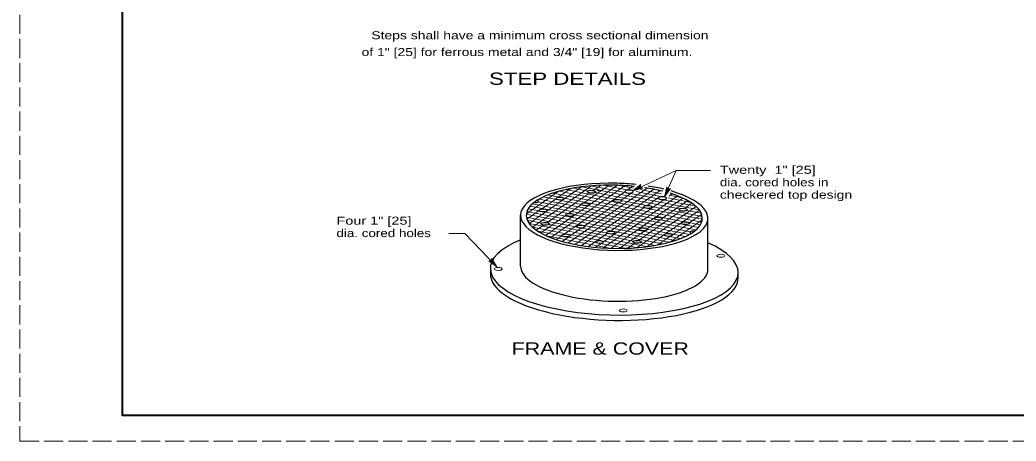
# Model space of a CAD drawing. Extents: x 1083.1 to 1117.1, y 697.4 to 741.4.
# Drawn here: x 1083.13 to 1102.54, y 697.35 to 705.57 of the extents above; entities that cross this region are included whole.
import ezdxf

# ---------------------------------------------------------------- set-up
doc = ezdxf.new("R2010")
doc.units = 0
doc.header["$LTSCALE"] = 0.062
doc.header["$PDMODE"] = 32
doc.header["$PDSIZE"] = 0.031
doc.linetypes.add('LONG_DASHED', pattern=[7.5, 6, -1.5])
doc.layers.add('1', color=7, linetype='Continuous', lineweight=13)

msp = doc.modelspace()

# ---------------------------------------------------------------- linework, layer by layer
at = {"layer": '1'}
for p, q in [((1095.07342, 702.23525), (1095.91408, 702.62967)), ((1095.69267, 702.11442), (1095.91408, 702.62967)), ((1095.91408, 702.62967), (1096.58942, 702.62967)), ((1093.05142, 701.59733), (1094.07375, 702.31042)), ((1093.11458, 701.52725), (1094.26708, 702.33117)), ((1093.37175, 701.36433), (1094.77217, 702.34108)), ((1093.47342, 701.32117), (1094.92583, 702.33417)), ((1093.61942, 702.10767), (1093.8635, 702.27783)), ((1093.81517, 701.21717), (1095.35017, 702.28783)), ((1093.91967, 702.28408), (1094.19808, 702.2295)), ((1094.08808, 702.30842), (1096.3665, 701.86133)), ((1094.11708, 701.99833), (1094.61067, 702.34258)), ((1094.95325, 702.19608), (1094.28575, 702.32708)), ((1094.30233, 702.24167), (1094.44392, 702.34042)), ((1094.50833, 702.34067), (1094.9835, 702.24742)), ((1094.80358, 702.34008), (1095.084, 702.28508)), ((1094.962, 702.24533), (1095.07308, 702.32275)), ((1095.22042, 702.33558), (1095.07342, 702.23525)), ((1095.2205, 702.322), (1095.07342, 702.23525)), ((1095.22442, 702.31), (1095.07342, 702.23525)), ((1095.23425, 702.29717), (1095.07342, 702.23525)), ((1095.24533, 702.28992), (1095.07342, 702.23525)), ((1095.74058, 702.28583), (1095.69267, 702.11442)), ((1095.74942, 702.2755), (1095.69267, 702.11442)), ((1095.76008, 702.26883), (1095.69267, 702.11442)), ((1095.789, 702.267), (1095.69267, 702.11442)), ((1092.99708, 701.78767), (1093.61467, 702.21842)), ((1093.291, 701.87858), (1093.57642, 702.07767)), ((1093.327, 702.11358), (1094.06642, 701.9685)), ((1093.40358, 701.61475), (1094.23233, 702.19283)), ((1093.4185, 702.153), (1093.63917, 702.10967)), ((1093.52167, 702.19017), (1093.91467, 702.113)), ((1093.63758, 702.22475), (1094.017, 702.15025)), ((1093.64242, 702.10908), (1093.64592, 702.10842)), ((1093.7335, 702.09117), (1096.0805, 701.63067)), ((1093.73633, 701.39042), (1094.91875, 702.21508)), ((1093.76775, 702.25658), (1094.11933, 702.18758)), ((1093.91467, 702.113), (1096.4125, 701.62292)), ((1093.94017, 701.19025), (1095.4805, 702.26467)), ((1094.017, 702.15025), (1096.42492, 701.67783)), ((1094.07058, 701.16708), (1095.6055, 702.23775)), ((1094.11933, 702.18758), (1094.75208, 702.06342)), ((1094.34042, 702.20158), (1095.98225, 701.87942)), ((1094.49492, 701.12075), (1095.94725, 702.13375)), ((1094.64858, 701.11375), (1096.049, 702.09058)), ((1094.84308, 702.04825), (1095.07242, 702.20825)), ((1094.95392, 702.19592), (1095.60658, 702.06783)), ((1095.13667, 702.21742), (1095.61, 702.1245)), ((1095.223, 702.25783), (1095.63433, 702.17708)), ((1095.35358, 701.94792), (1095.6115, 702.12775)), ((1095.77583, 702.26533), (1095.69267, 702.11442)), ((1095.72842, 702.09517), (1095.73308, 702.09842)), ((1095.764, 702.09425), (1096.19967, 702.00883)), ((1095.77758, 702.1295), (1095.83917, 702.17242)), ((1095.78458, 702.14767), (1096.02908, 702.09967)), ((1093.03333, 701.88442), (1093.25467, 701.841)), ((1093.07033, 701.9345), (1093.80933, 701.7895)), ((1093.11842, 701.98242), (1096.174, 701.38292)), ((1093.23042, 702.01783), (1096.19025, 701.43708)), ((1093.24675, 702.072), (1096.30233, 701.47242)), ((1093.82, 701.79108), (1094.06875, 701.96458)), ((1094.12558, 701.54775), (1094.78442, 702.00733)), ((1094.183, 701.94567), (1095.49433, 701.68833)), ((1094.502, 701.23975), (1095.68442, 702.0645)), ((1094.63633, 701.44758), (1095.29517, 701.90717)), ((1094.84758, 702.04467), (1095.34375, 701.94733)), ((1095.1575, 701.12642), (1096.30617, 701.92758)), ((1095.439, 701.92867), (1096.42317, 701.7355)), ((1095.62392, 702.06442), (1096.30208, 701.93133)), ((1095.64917, 701.69758), (1096.14358, 702.04242)), ((1096.0785, 701.89158), (1096.22375, 701.99283)), ((1092.99575, 701.77708), (1095.78317, 701.23017)), ((1092.99758, 701.71933), (1093.98175, 701.52625)), ((1093.00725, 701.68067), (1093.24783, 701.84842)), ((1093.00817, 701.832), (1095.89908, 701.26475)), ((1093.27717, 701.41242), (1093.7715, 701.75725)), ((1093.34017, 701.82425), (1095.69458, 701.36225)), ((1093.92642, 701.76658), (1095.23767, 701.50925)), ((1095.181, 701.2655), (1096.00783, 701.84225)), ((1095.34967, 701.14642), (1096.36933, 701.85758)), ((1096.12408, 701.85158), (1096.40483, 701.7965)), ((1096.17292, 701.60642), (1096.4135, 701.77425)), ((1093.01583, 701.65842), (1093.29667, 701.60333)), ((1093.05417, 701.5935), (1095.33967, 701.14508)), ((1093.11867, 701.5235), (1093.79675, 701.3905)), ((1093.19083, 701.46633), (1093.33225, 701.565)), ((1093.4385, 701.5755), (1095.08333, 701.25275)), ((1093.69558, 701.24792), (1094.06708, 701.507)), ((1094.07692, 701.50758), (1094.57308, 701.41025)), ((1095.352, 701.49033), (1095.60067, 701.66383)), ((1095.61133, 701.66542), (1096.35042, 701.52033)), ((1095.80608, 701.2365), (1096.42367, 701.66725)), ((1095.84425, 701.37725), (1096.12975, 701.57633)), ((1096.16608, 701.61392), (1096.38733, 701.5705)), ((1093.22108, 701.44608), (1093.69958, 701.35217)), ((1093.39167, 701.35525), (1094.61708, 701.11483)), ((1093.58383, 701.28408), (1093.69233, 701.35967)), ((1093.783, 701.33583), (1094.35333, 701.22392)), ((1093.81417, 701.38708), (1094.452, 701.26192)), ((1094.20633, 701.14767), (1094.57767, 701.40667)), ((1094.66867, 701.3915), (1095.653, 701.19833)), ((1094.80933, 701.11183), (1095.30358, 701.45658)), ((1095.35425, 701.48642), (1096.09367, 701.34133)), ((1095.56083, 701.17958), (1095.80133, 701.34725)), ((1095.78158, 701.34517), (1096.00225, 701.30192)), ((1094.34767, 701.13217), (1094.45867, 701.20958)), ((1094.43717, 701.2075), (1094.916, 701.1135)), ((1094.46683, 701.259), (1095.14683, 701.12558)), ((1094.96533, 701.11508), (1095.11033, 701.21625)), ((1095.22517, 701.22492), (1095.50633, 701.16975)), ((1092.28708, 700.86283), (1092.424, 700.74917)), ((1092.29508, 700.61825), (1092.29508, 700.718)), ((1092.30008, 700.86667), (1092.424, 700.74917)), ((1092.3105, 700.87367), (1092.424, 700.74917)), ((1092.32017, 700.88667), (1092.424, 700.74917)), ((1092.32408, 700.89933), (1092.424, 700.74917)), ((1097.12567, 700.54075), (1097.12567, 700.64017))]:
    msp.add_line(p, q, dxfattribs=at)
at = {"layer": '1', "lineweight": 25}
for p, q in [((1092.88458, 700.76483), (1092.88458, 701.75692)), ((1096.53617, 700.70675), (1096.53617, 701.698))]:
    msp.add_line(p, q, dxfattribs=at)
at = {"layer": '1', "linetype": 'LONG_DASHED'}
msp.add_lwpolyline([(1083.12642, 697.35408), (1117.12642, 697.35408), (1117.12642, 719.35408), (1083.12642, 719.35408)], close=True, dxfattribs=at)
at = {"layer": '1', "lineweight": 25}
msp.add_lwpolyline([(1116.62642, 697.85408), (1085.12642, 697.85408), (1085.12642, 718.85408)], dxfattribs=at)
at = {"layer": '1', "lineweight": 40}
msp.add_lwpolyline([(1085.12642, 718.85408), (1116.62642, 718.85408), (1116.62642, 697.85408), (1085.12642, 697.85408)], close=True, dxfattribs=at)
at = {"layer": '1'}
for points in [[(1095.26517, 702.28675), (1095.07342, 702.23525), (1095.23067, 702.35658)], [(1095.80625, 702.27725), (1095.69267, 702.11442), (1095.73492, 702.30842)], [(1092.424, 700.74917), (1091.79533, 701.40233), (1091.48725, 701.40233)], [(1092.32167, 700.91933), (1092.424, 700.74917), (1092.26408, 700.86683)]]:
    msp.add_lwpolyline(points, dxfattribs=at)
for centre, start, end in [((1095.26199, 702.32866), 138.42724, 274.25336), ((1095.77686, 702.30729), 178.49576, 314.32189), ((1092.28227, 700.90468), 244.41536, 20.24149)]:
    msp.add_arc(centre, 0.04202, start, end, dxfattribs=at)
at = {"layer": '1', "lineweight": 25}
for centre, major_axis, start_param, end_param in [((1094.71036, 701.72745), (-1.82577, 0.03378), 4.68824875, 10.3514373), ((1094.71036, 701.72745), (-1.71566, 0.03174), 4.74643531, 10.31477914), ((1094.71036, 701.72745), (-1.71566, 0.03174), 4.48528674, 4.74643594), ((1094.71036, 701.72745), (-1.82577, 0.03378), 4.48112461, 4.68824793), ((1094.71036, 701.72745), (-1.71566, 0.03174), 4.13484043, 4.36643568), ((1094.71036, 701.72745), (-1.82577, 0.03378), 4.16168417, 4.34880054), ((1093.65452, 702.08154), (0.07937, -0.00147), 1.54638911, 7.82956787), ((1094.2661, 702.21578), (0.07937, -0.00147), 3.30972366, 9.59288706), ((1094.99671, 702.21916), (0.07937, -0.00147), 1.37720252, 7.06035982), ((1094.99671, 702.21916), (0.07937, -0.00147), 0.77715614, 1.37720252), ((1095.6506, 702.0908), (0.07937, -0.00147), 2.12744926, 8.27550139), ((1093.17741, 702.02839), (-0.05953, 0.0011), 1.12902596, 4.23593116), ((1096.2433, 701.42651), (-0.05953, 0.0011), 4.27059689, 7.37752866), ((1094.71036, 700.67907), (-2.41522, 0.04469), 5.85576809, 10.1451119), ((1094.71036, 700.67907), (-2.41522, 0.04469), 5.57611175, 5.85576794), ((1094.71036, 700.73618), (-1.82577, 0.03378), 0.00541687, 3.1482218), ((1094.71032, 700.57423), (-2.41522, 0.04469), 0.00080736, 3.15452496)]:
    msp.add_ellipse(centre, major_axis=major_axis, ratio=0.358382, start_param=start_param, end_param=end_param, dxfattribs=at)
for centre, major_axis in [((1093.32585, 701.85243), (0.07937, -0.00147)), ((1094.14504, 701.97123), (0.07937, -0.00147)), ((1094.77349, 702.03567), (0.07937, -0.00147)), ((1095.36496, 701.91955), (0.07937, -0.00147)), ((1096.05255, 701.86507), (0.07937, -0.00147)), ((1093.84775, 701.76399), (-0.07937, 0.00147)), ((1095.57297, 701.69091), (0.07937, -0.00147)), ((1093.36816, 701.58983), (-0.07937, 0.00147)), ((1094.05576, 701.53535), (-0.07937, 0.00147)), ((1095.27567, 701.48367), (-0.07937, 0.00147)), ((1096.09486, 701.60247), (-0.07937, 0.00147)), ((1093.77012, 701.36411), (-0.07937, 0.00147)), ((1094.64722, 701.41923), (-0.07937, 0.00147)), ((1095.7662, 701.37336), (-0.07937, 0.00147)), ((1094.424, 701.23574), (-0.07937, 0.00147)), ((1095.15462, 701.23913), (-0.07937, 0.00147))]:
    msp.add_ellipse(centre, major_axis=major_axis, ratio=0.358382, dxfattribs=at)
at = {"layer": '1'}
for centre, major_axis in [((1096.78823, 700.96693), (0.07937, -0.00147)), ((1092.4474, 700.71025), (-0.07937, 0.00147)), ((1094.88494, 699.90137), (-0.07937, 0.00147))]:
    msp.add_ellipse(centre, major_axis=major_axis, ratio=0.358382, dxfattribs=at)
msp.add_point((1094.40083, 702.24708), dxfattribs=at)

# ---------------------------------------------------------------- texts
for s, height, width, p in [('Steps shall have a minimum cross sectional dimension', 0.156, 1.3, (1089.97533, 705.18867)), ('of 1" [25] for ferrous metal and 3/4" [19] for aluminum.', 0.156, 1.3, (1089.78592, 704.86125)), ('STEP DETAILS', 0.24, 1.35, (1092.26983, 704.30008)), ('Twenty  1" [25]', 0.156, 1.35, (1096.769, 702.56492)), ('dia. cored holes in', 0.156, 1.25, (1096.769, 702.32242)), ('checkered top design', 0.156, 1.3, (1096.769, 702.07992)), ('Four 1" [25]', 0.156, 1.35, (1089.29625, 701.57358)), ('dia. cored holes', 0.156, 1.25, (1089.29625, 701.33108)), ('FRAME & COVER', 0.24, 1.3, (1092.71067, 699.03908))]:
    msp.add_text(s, height=height, dxfattribs=dict(at, width=width)).set_placement(p)

doc.saveas('drawing.dxf')
